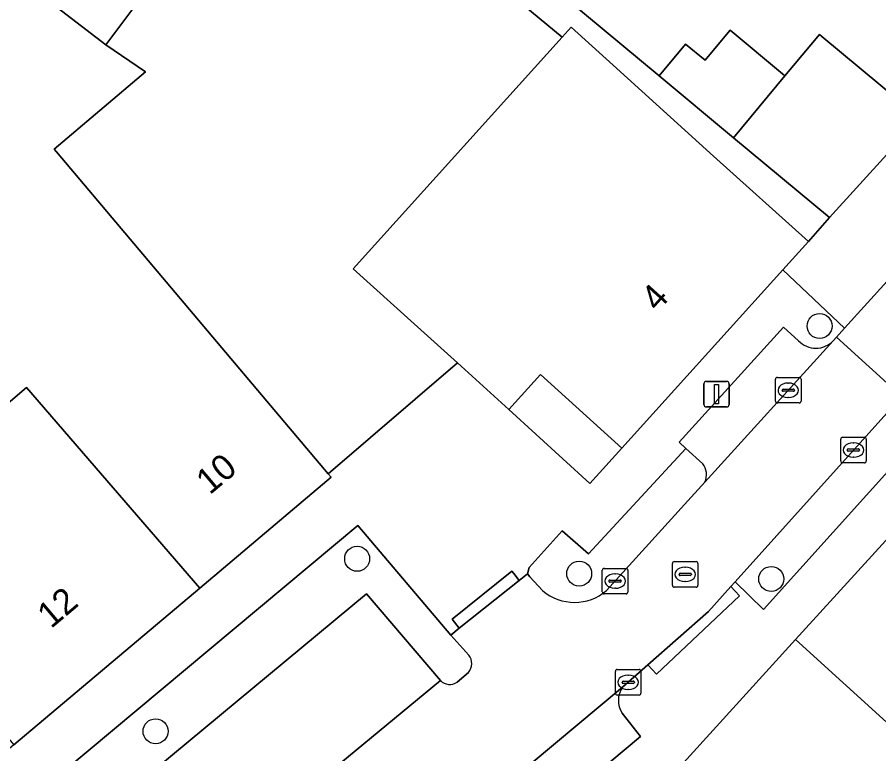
# Model space of a CAD drawing. Extents: x 161881 to 162523, y 381678 to 382381.
# Drawn here: x 162331.26 to 162365, y 381897.16 to 381925.99 of the extents above; entities that cross this region are included whole.
import ezdxf

# ---------------------------------------------------------------- set-up
doc = ezdxf.new("R2010")
doc.units = 0
for name, color, linetype in [('IMGEO_Boom', 7, 'Continuous'), ('IMGEO_Erf', 7, 'Continuous'), ('IMGEO_Groenvoorziening', 7, 'Continuous'), ('IMGEO_Kolk', 7, 'Continuous'), ('IMGEO_Lichtmast', 7, 'Continuous'), ('IMGEO_Pand', 7, 'Continuous'), ('IMGEO_Pand_nummerreeks', 7, 'Continuous'), ('IMGEO_Pand_overbouw', 7, 'Continuous'), ('IMGEO_Parkeervlak_open', 7, 'Continuous'), ('IMGEO_Rijbaan_lokaal_open', 7, 'Continuous'), ('IMGEO_Rioolput', 7, 'Continuous'), ('IMGEO_Voetpad_open', 7, 'Continuous')]:
    doc.layers.add(name, color=color, linetype=linetype)

msp = doc.modelspace()

# ---------------------------------------------------------------- linework, layer by layer
at = {"layer": 'IMGEO_Boom'}
for centre in [(162362.681, 381913.904), (162344.569, 381904.793), (162353.264, 381904.214), (162360.784, 381904.006), (162336.672, 381898.043)]:
    msp.add_circle(centre, 0.489, dxfattribs=at)
at = {"layer": 'IMGEO_Erf'}
for points in [[(162348.389, 381930.351), (162356.398, 381923.694), (162357.433, 381924.94), (162358.195, 381924.306), (162358.637, 381924.838), (162359.171, 381925.481), (162361.224, 381923.775), (162361.323, 381923.692), (162362.67, 381925.315), (162362.768, 381925.233), (162366.613, 381922.037)], [(162336.256, 381926.959), (162334.722, 381924.911), (162336.276, 381923.854), (162332.702, 381920.828), (162332.799, 381920.714), (162340.325, 381911.802), (162343.439, 381908.114), (162348.493, 381912.458), (162346.798, 381913.989), (162344.408, 381916.147), (162352.593, 381925.207), (162347.578, 381929.375)], [(162365.442, 381898.267), (162361.741, 381901.629), (162341.358, 381879.213)]]:
    msp.add_lwpolyline(points, dxfattribs=at)
msp.add_lwpolyline([(162351.747, 381912.009), (162350.508, 381910.637), (162353.682, 381907.742), (162354.94, 381909.125)], close=True, dxfattribs=at)
at = {"layer": 'IMGEO_Groenvoorziening'}
msp.add_lwpolyline([(162367.357, 381910.439), (162366.189, 381911.476), (162365.896, 381911.151), (162359.367, 381903.893), (162360.479, 381902.81)], close=True, dxfattribs=at)
for points in [[(162358.106, 381908.515), (162357.444, 381909.116), (162353.626, 381904.992), (162352.601, 381905.888), (162351.3, 381904.448), (162351.235, 381904.201), (162351.334, 381904.087), (162351.834, 381903.55)], [(162357.389, 381906.913), (162358.189, 381907.794)], [(162354.336, 381903.551), (162357.389, 381906.913)], [(162348.945, 381901.024), (162348.241, 381901.811), (162344.595, 381906.095), (162320.529, 381886.009), (162323.31, 381882.715), (162324.26, 381881.623)], [(162326.524, 381883.594), (162324.21, 381886.239), (162333.494, 381893.939), (162344.935, 381903.424)], [(162344.935, 381903.424), (162347.83, 381900.027)], [(162348.484, 381899.967), (162348.931, 381900.348)]]:
    msp.add_lwpolyline(points, dxfattribs=at)
for centre, radius, start, end in [((162357.522, 381908.083), 0.727, 336.6074, 36.5263), ((162353.084, 381905.011), 1.923, 229.4438, 310.602), ((162348.51, 381900.695), 0.545, 320.5007, 37.1265), ((162348.193, 381900.385), 0.509, 224.6131, 304.9033)]:
    msp.add_arc(centre, radius, start, end, dxfattribs=at)
at = {"layer": 'IMGEO_Kolk'}
for p, q in [((162360.951, 381910.965), (162360.951, 381911.817)), ((162361.026, 381911.891), (162361.878, 381911.891)), ((162361.952, 381911.817), (162361.952, 381910.965)), ((162361.253, 381911.434), (162361.651, 381911.434)), ((162361.439, 381911.671), (162361.464, 381911.671)), ((162361.21, 381911.385), (162361.21, 381911.397)), ((162361.648, 381911.348), (162361.25, 381911.348)), ((162361.462, 381911.111), (162361.437, 381911.111)), ((162361.694, 381911.397), (162361.694, 381911.385)), ((162361.878, 381910.891), (162361.026, 381910.891)), ((162363.506, 381908.623), (162363.506, 381909.475)), ((162363.581, 381909.549), (162364.433, 381909.549)), ((162364.507, 381909.475), (162364.507, 381908.623)), ((162363.765, 381909.043), (162363.765, 381909.055)), ((162363.808, 381909.092), (162364.206, 381909.092)), ((162363.994, 381909.329), (162364.019, 381909.329)), ((162364.249, 381909.055), (162364.249, 381909.043)), ((162364.203, 381909.006), (162363.805, 381909.006)), ((162364.017, 381908.769), (162363.992, 381908.769)), ((162364.433, 381908.549), (162363.581, 381908.549)), ((162354.171, 381903.494), (162354.171, 381904.346)), ((162354.246, 381904.42), (162355.098, 381904.42)), ((162355.172, 381904.346), (162355.172, 381903.494)), ((162354.659, 381904.2), (162354.684, 381904.2)), ((162354.43, 381903.914), (162354.43, 381903.926)), ((162354.868, 381903.877), (162354.47, 381903.877)), ((162354.473, 381903.963), (162354.871, 381903.963)), ((162354.914, 381903.926), (162354.914, 381903.914)), ((162355.098, 381903.42), (162354.246, 381903.42)), ((162354.682, 381903.64), (162354.657, 381903.64)), ((162354.683, 381899.536), (162354.683, 381900.388)), ((162354.758, 381900.462), (162355.61, 381900.462)), ((162355.684, 381900.388), (162355.684, 381899.536)), ((162354.942, 381899.956), (162354.942, 381899.968)), ((162354.985, 381900.005), (162355.383, 381900.005)), ((162355.171, 381900.242), (162355.196, 381900.242)), ((162355.426, 381899.968), (162355.426, 381899.956)), ((162355.38, 381899.919), (162354.982, 381899.919)), ((162355.194, 381899.682), (162355.169, 381899.682)), ((162355.61, 381899.462), (162354.758, 381899.462))]:
    msp.add_line(p, q, dxfattribs=at)
for points in [[(162360.951, 381910.965), (162360.951, 381911.817)], [(162361.026, 381911.891), (162361.878, 381911.891)], [(162361.952, 381911.817), (162361.952, 381910.965)], [(162361.878, 381910.891), (162361.026, 381910.891)], [(162363.506, 381908.623), (162363.506, 381909.475)], [(162363.581, 381909.549), (162364.433, 381909.549)], [(162364.507, 381909.475), (162364.507, 381908.623)], [(162364.433, 381908.549), (162363.581, 381908.549)], [(162354.171, 381903.494), (162354.171, 381904.346)], [(162354.246, 381904.42), (162355.098, 381904.42)], [(162355.172, 381904.346), (162355.172, 381903.494)], [(162355.098, 381903.42), (162354.246, 381903.42)], [(162354.683, 381899.536), (162354.683, 381900.388)], [(162354.758, 381900.462), (162355.61, 381900.462)], [(162355.684, 381900.388), (162355.684, 381899.536)], [(162355.61, 381899.462), (162354.758, 381899.462)]]:
    msp.add_lwpolyline(points, dxfattribs=at)
for centre, radius, start, end in [((162361.028, 381911.815), 0.0765, 91.552, 178.448), ((162361.028, 381911.815), 0.0765, 91.552, 178.448), ((162361.876, 381911.815), 0.0765, 1.552, 88.448), ((162361.876, 381911.815), 0.0765, 1.552, 88.448), ((162361.25, 381911.394), 0.0403, 85.8775, 175.7526), ((162361.655, 381911.396), 0.0386, 1.7309, 96.639), ((162361.247, 381911.384), 0.0366, 178.938, 274.7102), ((162361.651, 381911.391), 0.043, 264.8664, 352.4533), ((162361.028, 381910.967), 0.0765, 181.552, 268.448), ((162361.028, 381910.967), 0.0765, 181.552, 268.448), ((162361.876, 381910.967), 0.0765, 271.552, 358.448), ((162361.876, 381910.967), 0.0765, 271.552, 358.448), ((162363.583, 381909.473), 0.0765, 91.552, 178.448), ((162363.583, 381909.473), 0.0765, 91.552, 178.448), ((162364.431, 381909.473), 0.0765, 1.552, 88.448), ((162364.431, 381909.473), 0.0765, 1.552, 88.448), ((162363.805, 381909.052), 0.0403, 85.8775, 175.7526), ((162364.21, 381909.054), 0.0386, 1.7309, 96.639), ((162363.802, 381909.042), 0.0366, 178.938, 274.7102), ((162364.206, 381909.049), 0.043, 264.8664, 352.4533), ((162363.583, 381908.625), 0.0765, 181.552, 268.448), ((162363.583, 381908.625), 0.0765, 181.552, 268.448), ((162364.431, 381908.625), 0.0765, 271.552, 358.448), ((162364.431, 381908.625), 0.0765, 271.552, 358.448), ((162354.248, 381904.344), 0.0765, 91.552, 178.448), ((162354.248, 381904.344), 0.0765, 91.552, 178.448), ((162355.096, 381904.344), 0.0765, 1.552, 88.448), ((162355.096, 381904.344), 0.0765, 1.552, 88.448), ((162354.47, 381903.923), 0.0403, 85.8775, 175.7526), ((162354.467, 381903.913), 0.0366, 178.938, 274.7102), ((162354.871, 381903.92), 0.043, 264.8664, 352.4533), ((162354.875, 381903.925), 0.0386, 1.7309, 96.639), ((162354.248, 381903.496), 0.0765, 181.552, 268.448), ((162354.248, 381903.496), 0.0765, 181.552, 268.448), ((162355.096, 381903.496), 0.0765, 271.552, 358.448), ((162355.096, 381903.496), 0.0765, 271.552, 358.448), ((162354.76, 381900.386), 0.0765, 91.552, 178.448), ((162354.76, 381900.386), 0.0765, 91.552, 178.448), ((162355.608, 381900.386), 0.0765, 1.552, 88.448), ((162355.608, 381900.386), 0.0765, 1.552, 88.448), ((162354.982, 381899.965), 0.0403, 85.8775, 175.7526), ((162354.979, 381899.955), 0.0366, 178.938, 274.7102), ((162355.383, 381899.962), 0.043, 264.8664, 352.4533), ((162355.387, 381899.967), 0.0386, 1.7309, 96.639), ((162354.76, 381899.538), 0.0765, 181.552, 268.448), ((162354.76, 381899.538), 0.0765, 181.552, 268.448), ((162355.608, 381899.538), 0.0765, 271.552, 358.448), ((162355.608, 381899.538), 0.0765, 271.552, 358.448)]:
    msp.add_arc(centre, radius, start, end, dxfattribs=at)
for centre, major_axis, ratio, start_param, end_param in [((162361.438, 381911.391), (-0.387, 0.002), 0.722429, 4.712389, 7.853982), ((162361.463, 381911.391), (-0.39, 0.002), 0.717154, 1.570796, 4.712389), ((162363.993, 381909.049), (-0.387, 0.002), 0.722429, 4.712389, 7.853982), ((162364.018, 381909.049), (-0.39, 0.002), 0.717154, 1.570796, 4.712389), ((162354.658, 381903.92), (-0.387, 0.002), 0.722429, 4.712389, 7.853982), ((162354.683, 381903.92), (-0.39, 0.002), 0.717154, 1.570796, 4.712389), ((162355.17, 381899.962), (-0.387, 0.002), 0.722429, 4.712389, 7.853982), ((162355.195, 381899.962), (-0.39, 0.002), 0.717154, 1.570796, 4.712389)]:
    msp.add_ellipse(centre, major_axis=major_axis, ratio=ratio, start_param=start_param, end_param=end_param, dxfattribs=at)
at = {"layer": 'IMGEO_Lichtmast'}
for p, q in [((162358.148, 381910.837), (162358.148, 381911.637)), ((162358.148, 381911.637), (162358.148, 381910.837)), ((162358.248, 381911.737), (162359.038, 381911.737)), ((162359.038, 381911.737), (162358.248, 381911.737)), ((162359.138, 381911.637), (162359.138, 381910.837)), ((162359.138, 381910.837), (162359.138, 381911.637)), ((162359.038, 381910.737), (162358.248, 381910.737)), ((162358.248, 381910.737), (162359.038, 381910.737))]:
    msp.add_line(p, q, dxfattribs=at)
msp.add_lwpolyline([(162358.568, 381911.612), (162358.718, 381911.612), (162358.718, 381910.862), (162358.568, 381910.862), (162358.568, 381911.612)], dxfattribs=at)
for centre, start, end in [((162358.248, 381911.637), 90, 180), ((162358.248, 381911.637), 90, 180), ((162359.038, 381911.637), 0, 90), ((162359.038, 381911.637), 360, 90), ((162358.248, 381910.837), 180, 270), ((162358.248, 381910.837), 180, 270), ((162359.038, 381910.837), 270, 0), ((162359.038, 381910.837), 270, 0)]:
    msp.add_arc(centre, 0.1, start, end, dxfattribs=at)
at = {"layer": 'IMGEO_Pand'}
for points in [[(162332.18, 381932.056), (162330.883, 381930.326), (162329.705, 381928.752), (162329.893, 381928.608), (162334.722, 381924.911), (162336.256, 381926.959), (162337.238, 381928.272)], [(162332.799, 381920.714), (162332.702, 381920.828), (162336.276, 381923.854), (162334.722, 381924.911), (162329.893, 381928.608), (162314.839, 381916.848), (162320.397, 381910.215), (162322.762, 381907.393), (162324.457, 381905.392), (162331.614, 381911.491), (162338.405, 381903.648), (162343.551, 381907.982), (162343.439, 381908.114), (162340.325, 381911.802)], [(162362.239, 381917.205), (162358.529, 381920.557), (162354.594, 381924.111), (162352.947, 381925.599), (162352.593, 381925.207), (162344.408, 381916.147), (162346.798, 381913.989), (162348.493, 381912.458), (162350.508, 381910.637), (162351.747, 381912.009), (162354.94, 381909.125), (162361.239, 381916.098)], [(162356.398, 381923.694), (162359.313, 381921.271), (162361.323, 381923.692), (162361.224, 381923.775), (162359.171, 381925.481), (162358.637, 381924.838), (162358.195, 381924.306), (162357.433, 381924.94)], [(162362.768, 381925.233), (162362.67, 381925.315), (162361.323, 381923.692), (162359.313, 381921.271), (162363.07, 381918.146), (162365.317, 381920.614), (162365.423, 381920.73), (162366.613, 381922.037)], [(162331.614, 381911.491), (162324.457, 381905.392), (162331.126, 381897.517), (162338.405, 381903.648)], [(162371.892, 381900.569), (162365.805, 381906.102), (162361.741, 381901.629), (162365.442, 381898.267), (162369.929, 381894.191), (162373.921, 381898.584), (162371.822, 381900.491)]]:
    msp.add_lwpolyline(points, close=True, dxfattribs=at)
at = {"layer": 'IMGEO_Pand_overbouw'}
msp.add_lwpolyline([(162351.747, 381912.009), (162350.508, 381910.637), (162353.682, 381907.742), (162354.94, 381909.125)], close=True, dxfattribs=at)
at = {"layer": 'IMGEO_Parkeervlak_open'}
for points in [[(162361.858, 381913.325), (162361.266, 381913.862), (162357.177, 381909.358), (162357.444, 381909.116), (162358.106, 381908.515)], [(162358.189, 381907.794), (162363.209, 381913.324)], [(162347.83, 381900.027), (162344.935, 381903.424), (162333.494, 381893.939), (162324.21, 381886.239), (162326.524, 381883.594)], [(162326.421, 381882.163), (162326.917, 381882.526), (162334.545, 381888.97), (162343.935, 381896.807), (162347.83, 381900.027)], [(162354.961, 381899.766), (162341.523, 381888.554)], [(162355.663, 381897.834), (162354.947, 381898.752)], [(162343.074, 381888.143), (162343.505, 381887.673), (162349.335, 381892.545), (162355.663, 381897.834)]]:
    msp.add_lwpolyline(points, dxfattribs=at)
for centre, radius, start, end in [((162362.534, 381913.968), 0.933, 223.5604, 316.3548), ((162357.522, 381908.083), 0.727, 336.6074, 36.5263), ((162355.707, 381899.249), 0.908, 145.2561, 213.1619)]:
    msp.add_arc(centre, radius, start, end, dxfattribs=at)
at = {"layer": 'IMGEO_Rijbaan_lokaal_open'}
msp.add_lwpolyline([(162370.672, 381916.467), (162368.155, 381918.773), (162367.769, 381918.348), (162363.656, 381913.817), (162363.341, 381913.47), (162365.896, 381911.151), (162366.189, 381911.476), (162370.278, 381916.028)], close=True, dxfattribs=at)
for points in [[(162354.961, 381899.766), (162355.955, 381900.643), (162358.327, 381902.737), (162359.203, 381903.711), (162359.367, 381903.893), (162365.896, 381911.151), (162363.341, 381913.47), (162363.209, 381913.324), (162358.189, 381907.794), (162357.389, 381906.913), (162354.336, 381903.551)], [(162351.834, 381903.55), (162351.334, 381904.087), (162351.235, 381904.201), (162350.917, 381903.949), (162348.565, 381902.085), (162348.241, 381901.811), (162348.945, 381901.024)], [(162348.931, 381900.348), (162348.484, 381899.967)], [(162347.83, 381900.027), (162343.935, 381896.807), (162334.545, 381888.97), (162326.917, 381882.526), (162326.421, 381882.163), (162325.647, 381881.529)], [(162332.821, 381881.145), (162333.045, 381881.362), (162338.101, 381885.656), (162338.152, 381885.699), (162341.523, 381888.554), (162354.961, 381899.766)]]:
    msp.add_lwpolyline(points, dxfattribs=at)
for centre, radius, start, end in [((162353.084, 381905.011), 1.923, 229.4438, 310.602), ((162348.51, 381900.695), 0.545, 320.5007, 37.1265), ((162348.193, 381900.385), 0.509, 224.6131, 304.9033)]:
    msp.add_arc(centre, radius, start, end, dxfattribs=at)
at = {"layer": 'IMGEO_Rioolput'}
for p, q in [((162356.99, 381904.682), (162357.842, 381904.682)), ((162356.915, 381903.756), (162356.915, 381904.608)), ((162357.403, 381904.462), (162357.428, 381904.462)), ((162357.916, 381904.608), (162357.916, 381903.756)), ((162357.174, 381904.176), (162357.174, 381904.188)), ((162357.612, 381904.139), (162357.214, 381904.139)), ((162357.217, 381904.225), (162357.615, 381904.225)), ((162357.658, 381904.188), (162357.658, 381904.176)), ((162357.842, 381903.682), (162356.99, 381903.682)), ((162357.426, 381903.902), (162357.401, 381903.902))]:
    msp.add_line(p, q, dxfattribs=at)
for points in [[(162356.99, 381904.682), (162357.842, 381904.682)], [(162356.915, 381903.756), (162356.915, 381904.608)], [(162357.916, 381904.608), (162357.916, 381903.756)], [(162357.842, 381903.682), (162356.99, 381903.682)]]:
    msp.add_lwpolyline(points, dxfattribs=at)
for centre, radius, start, end in [((162356.992, 381904.606), 0.0765, 91.552, 178.448), ((162356.992, 381904.606), 0.0765, 91.552, 178.448), ((162357.84, 381904.606), 0.0765, 1.552, 88.448), ((162357.84, 381904.606), 0.0765, 1.552, 88.448), ((162357.214, 381904.185), 0.0403, 85.8775, 175.7526), ((162357.211, 381904.175), 0.0366, 178.938, 274.7102), ((162357.615, 381904.182), 0.043, 264.8664, 352.4533), ((162357.619, 381904.187), 0.0386, 1.7309, 96.639), ((162356.992, 381903.758), 0.0765, 181.552, 268.448), ((162356.992, 381903.758), 0.0765, 181.552, 268.448), ((162357.84, 381903.758), 0.0765, 271.552, 358.448), ((162357.84, 381903.758), 0.0765, 271.552, 358.448)]:
    msp.add_arc(centre, radius, start, end, dxfattribs=at)
for centre, major_axis, ratio, start_param, end_param in [((162357.402, 381904.182), (-0.387, 0.002), 0.722429, 4.712389, 7.853982), ((162357.427, 381904.182), (-0.39, 0.002), 0.717154, 1.570796, 4.712389)]:
    msp.add_ellipse(centre, major_axis=major_axis, ratio=ratio, start_param=start_param, end_param=end_param, dxfattribs=at)
at = {"layer": 'IMGEO_Voetpad_open'}
for points in [[(162352.593, 381925.207), (162352.947, 381925.599), (162354.594, 381924.111), (162358.529, 381920.557), (162362.239, 381917.205), (162363.07, 381918.146), (162359.313, 381921.271), (162356.398, 381923.694), (162348.389, 381930.351), (162347.578, 381929.375)], [(162363.656, 381913.817), (162367.769, 381918.348), (162365.317, 381920.614), (162363.07, 381918.146), (162362.239, 381917.205), (162361.239, 381916.098)], [(162350.917, 381903.949), (162350.701, 381904.214), (162350.624, 381904.311), (162348.285, 381902.431), (162348.565, 381902.085)], [(162359.203, 381903.711), (162358.327, 381902.737), (162355.955, 381900.643), (162356.298, 381900.28), (162359.546, 381903.348)]]:
    msp.add_lwpolyline(points, close=True, dxfattribs=at)
for points in [[(162363.209, 381913.324), (162363.341, 381913.47), (162363.656, 381913.817), (162361.239, 381916.098), (162354.94, 381909.125), (162353.682, 381907.742), (162350.508, 381910.637), (162348.493, 381912.458), (162343.439, 381908.114), (162343.551, 381907.982), (162338.405, 381903.648), (162331.126, 381897.517), (162320.508, 381888.575)], [(162357.444, 381909.116), (162357.177, 381909.358), (162361.266, 381913.862), (162361.858, 381913.325)], [(162340.416, 381878.177), (162341.358, 381879.213), (162361.741, 381901.629), (162365.805, 381906.102), (162368.679, 381909.266), (162367.357, 381910.439), (162360.479, 381902.81), (162359.367, 381903.893), (162359.203, 381903.711), (162359.546, 381903.348), (162356.298, 381900.28), (162355.955, 381900.643), (162354.961, 381899.766)], [(162320.529, 381886.009), (162344.595, 381906.095), (162348.241, 381901.811), (162348.565, 381902.085), (162348.285, 381902.431), (162350.624, 381904.311), (162350.701, 381904.214), (162350.917, 381903.949), (162351.235, 381904.201), (162351.3, 381904.448), (162352.601, 381905.888), (162353.626, 381904.992), (162357.444, 381909.116)], [(162354.947, 381898.752), (162355.663, 381897.834), (162349.335, 381892.545), (162350.082, 381891.85), (162347.971, 381889.246), (162341.733, 381882.383), (162338.101, 381885.656), (162333.045, 381881.362), (162332.821, 381881.145), (162337.02, 381877.264), (162327.942, 381867.176), (162325.146, 381864.385), (162324.203, 381865.309), (162323.422, 381864.435), (162320.231, 381860.917), (162320.6, 381860.581), (162318.083, 381857.819), (162317.714, 381858.155)]]:
    msp.add_lwpolyline(points, dxfattribs=at)
for centre, radius, start, end in [((162362.534, 381913.968), 0.933, 223.5604, 316.3548), ((162355.707, 381899.249), 0.908, 145.2561, 213.1619)]:
    msp.add_arc(centre, radius, start, end, dxfattribs=at)

# ---------------------------------------------------------------- texts
at = {"layer": 'IMGEO_Pand_nummerreeks'}
for s, rotation, p in [('4', 47.905, (162356.336, 381914.428)), ('10', 40.107, (162338.795, 381907.271)), ('12', 40.107, (162332.578, 381902.035))]:
    msp.add_text(s, height=1, rotation=rotation, dxfattribs=at).set_placement(p)

doc.saveas('drawing.dxf')
